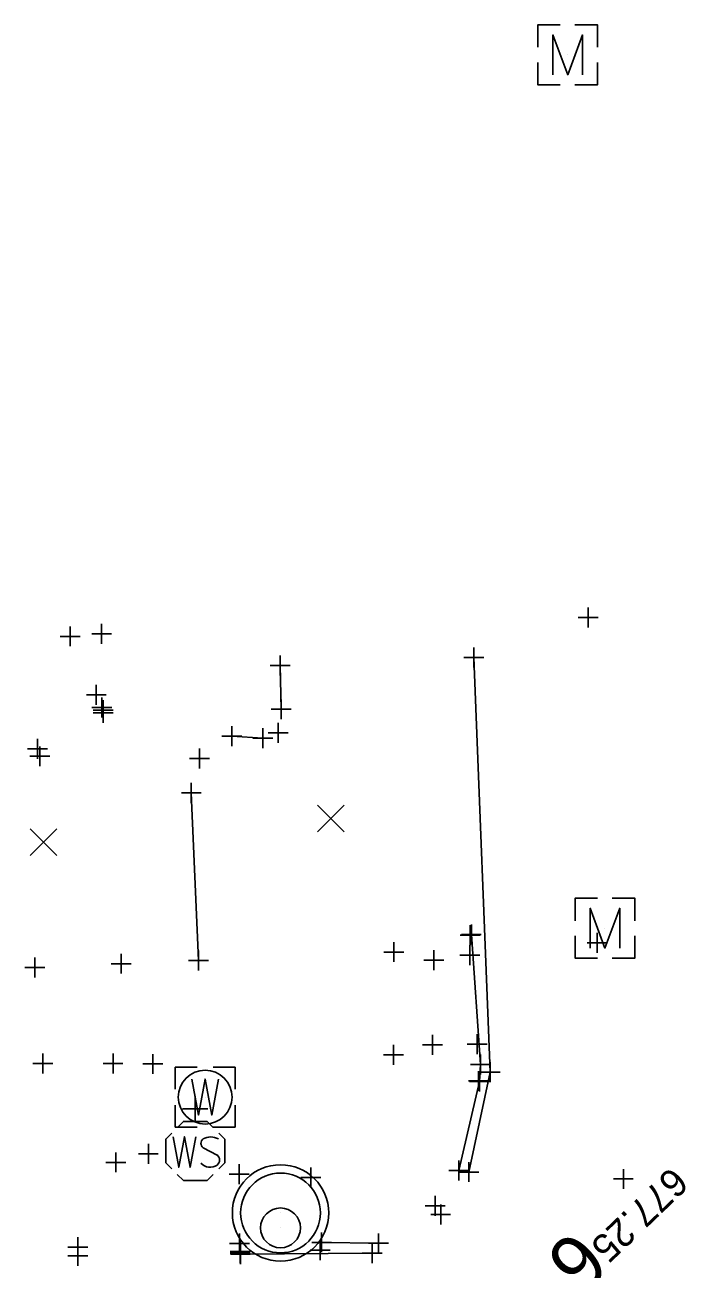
# Model space of a CAD drawing. Extents: x 2188719 to 2189819, y 654569 to 659504.
# Drawn here: x 2188987.7 to 2189020.9, y 655617.7 to 655680.1 of the extents above; entities that cross this region are included whole.
import ezdxf

# ---------------------------------------------------------------- set-up
doc = ezdxf.new("R2010")
doc.units = 0
for name, color, linetype in [('Default', 7, 'Continuous'), ('DR_X_Cells', 7, 'Continuous'), ('DR_X_Text', 7, 'Continuous'), ('GK_Drainage_Nodes', 7, 'Continuous'), ('PV_X_Curb', 7, 'Continuous'), ('PV_X_EOP', 7, 'Continuous'), ('PV_X_Walk', 7, 'Continuous'), ('SC_Scratch1', 7, 'Continuous'), ('SV_X_LiDAR_Check_Spots', 7, 'Continuous'), ('SV_X_Mon_Cells_Found', 7, 'Continuous'), ('SV_X_Random_Point', 7, 'Continuous'), ('SV_X_Shot_Marker', 7, 'Continuous'), ('UT_X_Water_Cells', 7, 'Continuous')]:
    doc.layers.add(name, color=color, linetype=linetype)

msp = doc.modelspace()

# ---------------------------------------------------------------- linework, layer by layer
at = {"layer": 'Default'}
msp.add_line((2189010.367, 655629.008), (2189010.367, 655629.008), dxfattribs=at)
at = {"layer": 'DR_X_Cells'}
for centre, radius in [((2189000.506, 655620.537), 2.417), ((2189000.506, 655620.537), 2), ((2189000.506, 655619.787), 1)]:
    msp.add_circle(centre, radius, dxfattribs=at)
at = {"layer": 'GK_Drainage_Nodes'}
for p, q in [((2189000.506, 655622.537), (2189000.506, 655622.537)), ((2189000.506, 655620.537), (2189000.506, 655620.537)), ((2189000.506, 655620.537), (2189000.506, 655620.537)), ((2189000.506, 655619.787), (2189000.506, 655619.787)), ((2189000.506, 655618.537), (2189000.506, 655618.537))]:
    msp.add_line(p, q, dxfattribs=at)
msp.add_circle((2189000.506, 655620.537), 2, dxfattribs=at)
at = {"layer": 'PV_X_Curb'}
for p, q in [((2189010.534, 655627.983), (2189010.081, 655634.507)), ((2189010.496, 655627.13), (2189010.534, 655627.983)), ((2189009.459, 655622.662), (2189010.496, 655627.13)), ((2189002.57, 655619.063), (2189005.425, 655619.014))]:
    msp.add_line(p, q, dxfattribs=at)
at = {"layer": 'PV_X_EOP'}
for p, q in [((2189011.028, 655627.603), (2189010.206, 655648.398)), ((2189009.95, 655622.59), (2189011.028, 655627.603)), ((2188998.491, 655618.474), (2189005.102, 655618.514))]:
    msp.add_line(p, q, dxfattribs=at)
at = {"layer": 'PV_X_Walk'}
for p, q in [((2189000.542, 655645.8), (2189000.484, 655647.995)), ((2188998.059, 655644.453), (2188999.614, 655644.346)), ((2188996.386, 655633.2), (2188996.03, 655641.615))]:
    msp.add_line(p, q, dxfattribs=at)
at = {"layer": 'SV_X_LiDAR_Check_Spots'}
for p, q in [((2189008.192, 655633.715), (2189008.192, 655632.715)), ((2189010.009, 655633.967), (2189010.009, 655632.967)), ((2189007.692, 655633.215), (2189008.692, 655633.215)), ((2189008.192, 655633.215), (2189008.192, 655633.215)), ((2189009.509, 655633.467), (2189010.509, 655633.467)), ((2189010.009, 655633.467), (2189010.009, 655633.467)), ((2189008.135, 655629.463), (2189008.135, 655628.463)), ((2189007.635, 655628.963), (2189008.635, 655628.963)), ((2189008.135, 655628.963), (2189008.135, 655628.963))]:
    msp.add_line(p, q, dxfattribs=at)
at = {"layer": 'SV_X_Mon_Cells_Found'}
for p, q in [((2189014.914, 655678.629), (2189014.914, 655678.629)), ((2189016.785, 655634.819), (2189016.785, 655634.819))]:
    msp.add_line(p, q, dxfattribs=at)
for points in [[(2189013.414, 655679.007), (2189013.414, 655680.131), (2189014.537, 655680.131)], [(2189015.269, 655680.131), (2189016.416, 655680.131), (2189016.416, 655679.007)], [(2189014.174, 655677.629), (2189014.174, 655679.629), (2189014.914, 655677.629), (2189015.654, 655679.629), (2189015.654, 655677.629)], [(2189014.537, 655677.129), (2189013.414, 655677.129), (2189013.414, 655678.251)], [(2189016.416, 655678.251), (2189016.416, 655677.129), (2189015.269, 655677.129)], [(2189015.285, 655635.197), (2189015.285, 655636.321), (2189016.408, 655636.321)], [(2189017.14, 655636.321), (2189018.287, 655636.321), (2189018.287, 655635.197)], [(2189016.045, 655633.819), (2189016.045, 655635.819), (2189016.785, 655633.819), (2189017.525, 655635.819), (2189017.525, 655633.819)], [(2189016.408, 655633.319), (2189015.285, 655633.319), (2189015.285, 655634.441)], [(2189018.287, 655634.441), (2189018.287, 655633.319), (2189017.14, 655633.319)]]:
    msp.add_lwpolyline(points, dxfattribs=at)
at = {"layer": 'SV_X_Random_Point'}
for p, q in [((2189002.36, 655639.655), (2189003.694, 655640.99)), ((2189002.36, 655640.99), (2189003.694, 655639.655)), ((2188987.952, 655638.473), (2188989.286, 655639.808)), ((2188987.952, 655639.808), (2188989.286, 655638.473))]:
    msp.add_line(p, q, dxfattribs=at)
at = {"layer": 'SV_X_Shot_Marker'}
for p, q in [((2189015.944, 655650.904), (2189015.944, 655649.904)), ((2188989.95, 655649.959), (2188989.95, 655648.959)), ((2188991.531, 655650.085), (2188991.531, 655649.085)), ((2189015.444, 655650.404), (2189016.444, 655650.404)), ((2189015.944, 655650.404), (2189015.944, 655650.404)), ((2188989.45, 655649.459), (2188990.45, 655649.459)), ((2188989.95, 655649.459), (2188989.95, 655649.459)), ((2188991.031, 655649.585), (2188992.031, 655649.585)), ((2188991.531, 655649.585), (2188991.531, 655649.585)), ((2189010.206, 655648.898), (2189010.206, 655647.898)), ((2188999.984, 655647.995), (2189000.984, 655647.995)), ((2189000.484, 655648.495), (2189000.484, 655647.495)), ((2189000.484, 655647.995), (2189000.484, 655647.995)), ((2189009.706, 655648.398), (2189010.706, 655648.398)), ((2189010.206, 655648.398), (2189010.206, 655648.398)), ((2188991.264, 655647.032), (2188991.264, 655646.032)), ((2188990.764, 655646.532), (2188991.764, 655646.532)), ((2188991.264, 655646.532), (2188991.264, 655646.532)), ((2188991.541, 655646.393), (2188991.541, 655645.393)), ((2188991.605, 655646.124), (2188991.605, 655645.124)), ((2188991.613, 655646.252), (2188991.613, 655645.252)), ((2189000.542, 655646.3), (2189000.542, 655645.3)), ((2188991.041, 655645.893), (2188992.041, 655645.893)), ((2188991.105, 655645.624), (2188992.105, 655645.624)), ((2188991.113, 655645.752), (2188992.113, 655645.752)), ((2188991.541, 655645.893), (2188991.541, 655645.893)), ((2188991.605, 655645.624), (2188991.605, 655645.624)), ((2188991.613, 655645.752), (2188991.613, 655645.752)), ((2189000.042, 655645.8), (2189001.042, 655645.8)), ((2189000.542, 655645.8), (2189000.542, 655645.8)), ((2188998.059, 655644.953), (2188998.059, 655643.953)), ((2188999.614, 655644.846), (2188999.614, 655643.846)), ((2189000.383, 655645.117), (2189000.383, 655644.117)), ((2188988.309, 655644.32), (2188988.309, 655643.32)), ((2188997.559, 655644.453), (2188998.559, 655644.453)), ((2188998.059, 655644.453), (2188998.059, 655644.453)), ((2188999.114, 655644.346), (2189000.114, 655644.346)), ((2188999.614, 655644.346), (2188999.614, 655644.346)), ((2188999.883, 655644.617), (2189000.883, 655644.617)), ((2189000.383, 655644.617), (2189000.383, 655644.617)), ((2188987.809, 655643.82), (2188988.809, 655643.82)), ((2188988.309, 655643.82), (2188988.309, 655643.82)), ((2188988.435, 655643.941), (2188988.435, 655642.941)), ((2188996.437, 655643.829), (2188996.437, 655642.829)), ((2188987.935, 655643.441), (2188988.935, 655643.441)), ((2188988.435, 655643.441), (2188988.435, 655643.441)), ((2188995.937, 655643.329), (2188996.937, 655643.329)), ((2188996.437, 655643.329), (2188996.437, 655643.329)), ((2188996.03, 655642.115), (2188996.03, 655641.115)), ((2188995.53, 655641.615), (2188996.53, 655641.615)), ((2188996.03, 655641.615), (2188996.03, 655641.615)), ((2189010.016, 655634.973), (2189010.016, 655633.973)), ((2189010.081, 655635.007), (2189010.081, 655634.007)), ((2189009.516, 655634.473), (2189010.516, 655634.473)), ((2189009.581, 655634.507), (2189010.581, 655634.507)), ((2189010.016, 655634.473), (2189010.016, 655634.473)), ((2189010.081, 655634.507), (2189010.081, 655634.507)), ((2189016.398, 655634.585), (2189016.398, 655633.585)), ((2188996.386, 655633.7), (2188996.386, 655632.7)), ((2189005.693, 655633.626), (2189006.693, 655633.626)), ((2189006.193, 655634.126), (2189006.193, 655633.126)), ((2189006.193, 655633.626), (2189006.193, 655633.626)), ((2189015.898, 655634.085), (2189016.898, 655634.085)), ((2189016.398, 655634.085), (2189016.398, 655634.085)), ((2188988.179, 655633.349), (2188988.179, 655632.349)), ((2188992.009, 655633.041), (2188993.009, 655633.041)), ((2188992.509, 655633.541), (2188992.509, 655632.541)), ((2188992.509, 655633.041), (2188992.509, 655633.041)), ((2188995.886, 655633.2), (2188996.886, 655633.2)), ((2188996.386, 655633.2), (2188996.386, 655633.2)), ((2188987.679, 655632.849), (2188988.679, 655632.849)), ((2188988.179, 655632.849), (2188988.179, 655632.849)), ((2189010.367, 655629.508), (2189010.367, 655628.508)), ((2189006.175, 655628.97), (2189006.175, 655627.97)), ((2189009.867, 655629.008), (2189010.867, 655629.008)), ((2189010.367, 655629.008), (2189010.367, 655629.008)), ((2188988.084, 655628.033), (2188989.084, 655628.033)), ((2188988.584, 655628.533), (2188988.584, 655627.533)), ((2188988.584, 655628.033), (2188988.584, 655628.033)), ((2188991.601, 655628.032), (2188992.601, 655628.032)), ((2188992.101, 655628.532), (2188992.101, 655627.532)), ((2188992.101, 655628.032), (2188992.101, 655628.032)), ((2188993.597, 655628.009), (2188994.597, 655628.009)), ((2188994.097, 655628.509), (2188994.097, 655627.509)), ((2188994.097, 655628.009), (2188994.097, 655628.009)), ((2189005.675, 655628.47), (2189006.675, 655628.47)), ((2189006.175, 655628.47), (2189006.175, 655628.47)), ((2189010.034, 655627.983), (2189011.034, 655627.983)), ((2189010.534, 655628.483), (2189010.534, 655627.483)), ((2189010.534, 655627.983), (2189010.534, 655627.983)), ((2189011.028, 655628.103), (2189011.028, 655627.103)), ((2189010.435, 655627.657), (2189010.435, 655626.657)), ((2189010.496, 655627.63), (2189010.496, 655626.63)), ((2189010.528, 655627.603), (2189011.528, 655627.603)), ((2189011.028, 655627.603), (2189011.028, 655627.603)), ((2189009.935, 655627.157), (2189010.935, 655627.157)), ((2189009.996, 655627.13), (2189010.996, 655627.13)), ((2189010.435, 655627.157), (2189010.435, 655627.157)), ((2189010.496, 655627.13), (2189010.496, 655627.13)), ((2188993.874, 655624), (2188993.874, 655623)), ((2188991.744, 655623.075), (2188992.744, 655623.075)), ((2188992.244, 655623.575), (2188992.244, 655622.575)), ((2188992.244, 655623.075), (2188992.244, 655623.075)), ((2188993.374, 655623.5), (2188994.374, 655623.5)), ((2188993.874, 655623.5), (2188993.874, 655623.5)), ((2188998.425, 655622.979), (2188998.425, 655621.979)), ((2189009.459, 655623.162), (2189009.459, 655622.162)), ((2189009.95, 655623.09), (2189009.95, 655622.09)), ((2188997.925, 655622.479), (2188998.925, 655622.479)), ((2188998.425, 655622.479), (2188998.425, 655622.479)), ((2189002.033, 655622.818), (2189002.033, 655621.818)), ((2189008.959, 655622.662), (2189009.959, 655622.662)), ((2189009.45, 655622.59), (2189010.45, 655622.59)), ((2189009.459, 655622.662), (2189009.459, 655622.662)), ((2189009.95, 655622.59), (2189009.95, 655622.59)), ((2189017.708, 655622.74), (2189017.708, 655621.74)), ((2189001.533, 655622.318), (2189002.533, 655622.318)), ((2189002.033, 655622.318), (2189002.033, 655622.318)), ((2189017.208, 655622.24), (2189018.208, 655622.24)), ((2189017.708, 655622.24), (2189017.708, 655622.24)), ((2189008.267, 655621.389), (2189008.267, 655620.389)), ((2189007.767, 655620.889), (2189008.767, 655620.889)), ((2189008.267, 655620.889), (2189008.267, 655620.889)), ((2189008.542, 655620.954), (2189008.542, 655619.954)), ((2189008.042, 655620.454), (2189009.042, 655620.454)), ((2189008.542, 655620.454), (2189008.542, 655620.454)), ((2188990.331, 655619.323), (2188990.331, 655618.323)), ((2188998.443, 655619.499), (2188998.443, 655618.499)), ((2189002.57, 655619.563), (2189002.57, 655618.563)), ((2189005.425, 655619.514), (2189005.425, 655618.514)), ((2188989.831, 655618.823), (2188990.831, 655618.823)), ((2188990.331, 655618.823), (2188990.331, 655618.823)), ((2188990.341, 655618.882), (2188990.341, 655617.882)), ((2188997.943, 655618.999), (2188998.943, 655618.999)), ((2188997.984, 655618.602), (2188998.984, 655618.602)), ((2188998.443, 655618.999), (2188998.443, 655618.999)), ((2188998.475, 655619.013), (2188998.475, 655618.013)), ((2188998.484, 655619.102), (2188998.484, 655618.102)), ((2188998.484, 655618.602), (2188998.484, 655618.602)), ((2188998.491, 655618.974), (2188998.491, 655617.974)), ((2189002.001, 655618.671), (2189003.001, 655618.671)), ((2189002.07, 655619.063), (2189003.07, 655619.063)), ((2189002.501, 655619.171), (2189002.501, 655618.171)), ((2189002.501, 655618.671), (2189002.501, 655618.671)), ((2189002.57, 655619.063), (2189002.57, 655619.063)), ((2189004.925, 655619.014), (2189005.925, 655619.014)), ((2189005.102, 655619.014), (2189005.102, 655618.014)), ((2189005.425, 655619.014), (2189005.425, 655619.014)), ((2188989.841, 655618.382), (2188990.841, 655618.382)), ((2188990.341, 655618.382), (2188990.341, 655618.382)), ((2188997.975, 655618.513), (2188998.975, 655618.513)), ((2188997.991, 655618.474), (2188998.991, 655618.474)), ((2188998.475, 655618.513), (2188998.475, 655618.513)), ((2188998.491, 655618.474), (2188998.491, 655618.474)), ((2189004.602, 655618.514), (2189005.602, 655618.514)), ((2189005.102, 655618.514), (2189005.102, 655618.514))]:
    msp.add_line(p, q, dxfattribs=at)
at = {"layer": 'UT_X_Water_Cells'}
for p, q in [((2188996.228, 655625.126), (2188996.228, 655626.396)), ((2188996.725, 655626.348), (2188996.725, 655626.348)), ((2188996.863, 655625.761), (2188995.59, 655625.761)), ((2188996.228, 655623.645), (2188996.228, 655623.645)), ((2188996.631, 655623.81), (2188997.333, 655623.443))]:
    msp.add_line(p, q, dxfattribs=at)
for points in [[(2188996.325, 655627.848), (2188995.225, 655627.848), (2188995.225, 655626.748)], [(2188998.225, 655626.748), (2188998.225, 655627.848), (2188997.125, 655627.848)], [(2188996.058, 655627.248), (2188996.392, 655625.448), (2188996.725, 655627.248), (2188997.058, 655625.448), (2188997.392, 655627.248)], [(2188995.225, 655625.948), (2188995.225, 655624.848), (2188996.325, 655624.848)], [(2188997.125, 655624.848), (2188998.225, 655624.848), (2188998.225, 655625.948)], [(2188997.125, 655624.821), (2188996.82, 655625.126), (2188995.635, 655625.126), (2188995.331, 655624.825)], [(2188995.051, 655624.541), (2188994.746, 655624.238), (2188994.746, 655623.053), (2188995.048, 655622.751)], [(2188995.12, 655624.355), (2188995.403, 655622.828), (2188995.685, 655624.355), (2188995.968, 655622.828), (2188996.255, 655624.355)], [(2188997.405, 655622.751), (2188997.708, 655623.053), (2188997.708, 655624.238), (2188997.405, 655624.541)], [(2188995.328, 655622.471), (2188995.635, 655622.165), (2188996.82, 655622.165), (2188997.125, 655622.468)]]:
    msp.add_lwpolyline(points, dxfattribs=at)
msp.add_circle((2188996.725, 655626.348), 1.35, dxfattribs=at)
for centre, radius, start, end in [((2188996.781, 655624.035), 0.271, 126.25873, 236.36755), ((2188997.005, 655623.551), 0.8, 61.34633, 118.65367), ((2188996.972, 655623.463), 0.633, 223.66947, 304.39628), ((2188997.105, 655623.195), 0.339, 311.48833, 47.93584)]:
    msp.add_arc(centre, radius, start, end, dxfattribs=at)

# ---------------------------------------------------------------- texts
at = {"layer": 'DR_X_Text'}
msp.add_text('6" VIT', height=2.8, rotation=223.82119, dxfattribs=at).set_placement((2189015.198, 655619.785))
at = {"layer": 'SC_Scratch1'}
msp.add_text('677.25', height=1.4, rotation=223.82119, dxfattribs=at).set_placement((2189020.115, 655622.916))

doc.saveas('drawing.dxf')
